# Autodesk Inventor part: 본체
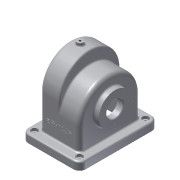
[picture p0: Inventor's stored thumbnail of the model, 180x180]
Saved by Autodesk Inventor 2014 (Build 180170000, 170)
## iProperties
Created: 2017-11
Part Number: 본체
Material: 알루미늄 6061
Document SubType Name: Modeling
Designer: user
Density: 2.71 g/cm^3
Appearance: 알루미늄 - 평지
Mass: 711.678 g
Surface Area: 1202.64 cm^2
Volume: 262.612 cm^3
Author: user
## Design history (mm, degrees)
sketch "스케치1"
  geometry: L1 (55, -75)-(-55, -75); L2 (-55, -75)-(-55, 75); L3 (-55, 75)-(55, 75); L4 (55, 75)-(55, -75); L5 (55, -75)-(-55, 75); L6 (-55, -75)-(55, 75); 1 further point
  constraints: 12 end point, 2 midpoint, 2 parallel, 1 horizontal, 1 perpendicular
  dimensions: "d0" = 110 distance of L1.start L1.end; "d1" = 150 distance of L1.end L2.end
extrude "돌출1" new body sketch "스케치1" distance "d2" = 15; taper "d3" = 0 deg
sketch "스케치2"
  geometry: L1 (-55, 15)-(55, 15) reference; L2 (-38, 15)-(-38, 138); L3 (-38, 138)-(0, 138); L4 (0, 138)-(0, 115); L5 (0, 115)-(38, 115); L6 (38, 115)-(38, 15); L7 (-55, 0)-(-55, 15) reference; L8 (-38, 15)-(38, 15); L9 (-5, 133)-(-33, 133); L10 (-33, 133)-(-33, 15); L11 (33, 15)-(33, 110); L12 (33, 110)-(-5, 110); L13 (-5, 110)-(-5, 133); 1 further point
  constraints: 22 end point, 4 parallel, 4 perpendicular, 4 point on line, 1 collinear, 1 other
  dimensions: "d4" = 76 horizontal distance of L5.end L2.end; "d5" = 38 distance of L2.end L3.end; "d6" = 55 distance from line of L3.end L7; "d13" = 5 distance between parallel lines of L3 L9; "d102" = 123 distance of L2.end L2.start; "d103" = 100 distance of L5.end L6.end
extrude "돌출2" new body sketch "스케치2" stored distance "d7" = 116; taper "d8" = 0 deg
fillet "모깎기1" dims "d9" = 58
fillet "모깎기2" dims "d10" = 58
fillet "모깎기3" dims "d11" = 3
fillet "모깎기4" dims "d12" = 8
feature "쉘1" dims "d14" = 2
sketch "스케치6"
  geometry: L1 (-30, 56)-(30, 56) reference; L2 (36, 50)-(36, -50) reference; L3 (-36, -50)-(-36, 50) reference; L4 (30, -56)-(-30, -56) reference; A1 r 6 centre (30, 50) between (36, 50) and (30, 56) reference; A2 r 6 centre (-30, 50) between (-30, 56) and (-36, 50) reference; A3 r 6 centre (-30, -50) between (-36, -50) and (-30, -56) reference; A4 r 6 centre (30, -50) between (30, -56) and (36, -50) reference; 1 further point
extrude "돌출3" cut sketch "스케치6" distance "d15" = 15; taper "d16" = 0 deg
fillet "모깎기5" dims "d17" = 12
hole "구멍1" diameter "d20" = 5; stored, may be unused: countersink angle "d24" = 90 deg, drill point angle "d26" = 0 deg; dims "d18" = 10, "d19" = 10, "d21" = 6, "d22" = 12, "d23" = 5, "d25" = 8
hole "구멍2" diameter "d29" = 5; stored, may be unused: countersink angle "d33" = 90 deg, drill point angle "d35" = 0 deg; dims "d27" = 10, "d28" = 10, "d30" = 6, "d31" = 12, "d32" = 5, "d34" = 8
hole "구멍3" diameter "d38" = 5; stored, may be unused: countersink angle "d42" = 90 deg, drill point angle "d44" = 0 deg; dims "d36" = 10, "d37" = 10, "d39" = 6, "d40" = 12, "d41" = 5, "d43" = 8
hole "구멍4" diameter "d47" = 5; stored, may be unused: countersink angle "d51" = 90 deg, drill point angle "d53" = 0 deg; dims "d45" = 10, "d46" = 10, "d48" = 6, "d49" = 12, "d50" = 5, "d52" = 8
fillet "모깎기6" dims "d54" = 3
sketch "스케치8"
  geometry: L1 (13, -15)-(-113, -15) reference; C1 r 31 at (-50, 50); A1 r 50 centre (-50, 42) between (0, 42) and (-100, 42) reference; 1 further point
  constraints: 1 centre point, 1 vertical alignment
  dimensions: "d59" = 65 distance from line of C1.centre L1; "d60" = 62 diameter of C1
extrude "돌출5" join sketch "스케치8" distance "d61" = 10; taper "d62" = 0 deg
fillet "모깎기8" dims "d63" = 3
sketch "스케치9"
  geometry: L1 (113, -15)-(-13, -15) reference; C1 r 37.5 at (50, 50); A1 r 50 centre (50, 65) between (100, 65) and (0, 65) reference; 1 further point
  constraints: 1 centre point, 1 vertical alignment
  dimensions: "d64" = 75 diameter of C1; "d65" = 65 distance from line of L1 C1.centre
extrude "돌출6" join sketch "스케치9" distance "d66" = 9; taper "d67" = 0 deg
fillet "모깎기9" dims "d68" = 3
sketch "스케치10" dims "d69" = 58
  geometry: C1 r 37.5 at (0, 0) reference; 3 further points
  constraints: 2 vertical alignment, 1 coincident, 2 other
hole "구멍5" sketch "스케치10" at (0, 29) diameter "d70" = 2; stored, may be unused: countersink angle "d74" = 82 deg, drill point angle "d76" = 118 deg; dims "d71" = 6, "d72" = 19, "d73" = 5, "d75" = 8
sketch "스케치11" dims "d80" = 52
  geometry: C1 r 31 at (0, 0) reference; 3 further points
  constraints: 2 vertical alignment, 1 coincident, 2 other
hole "구멍6" sketch "스케치11" at (0, 26) diameter "d81" = 2; stored, may be unused: countersink angle "d85" = 82 deg, drill point angle "d87" = 118 deg; dims "d82" = 6, "d83" = 19, "d84" = 5, "d86" = 8
sketch "스케치12"
  geometry: C1 r 37.5 at (0, 0) reference; C2 r 16 at (0, 0); 1 further point
  constraints: 1 centre point, 1 coincident
  dimensions: "d91" = 32 diameter of C2
extrude "돌출7" cut sketch "스케치12" stored distance "d92" = 9; taper "d93" = 0 deg
chamfer "모따기1" distance "d94" = 1; stored, may be unused: second distance "d95" = 2, angle "d96" = 45 deg
node "작업 평면1"
sketch "스케치13"
  geometry: L1 (38, 50)-(38, -50) reference; C1 r 6 at (19, 0); 1 further point
  constraints: 1 centre point, 1 horizontal alignment
  dimensions: "d98" = 12 diameter of C1; "d99" = 19 distance from line of C1.centre L1
extrude "돌출9" join sketch "스케치13" distance "d104" = 9; taper "d105" = 0 deg
fillet "모깎기10" dims "d106" = 3
hole "구멍7" diameter "d109" = 4; stored, may be unused: countersink angle "d113" = 82 deg, drill point angle "d115" = 118 deg; dims "d107" = 10, "d108" = 10, "d110" = 6, "d111" = 19, "d112" = 5, "d114" = 8
sketch "스케치14"
  geometry: L1 (43, 0)-(-43, 0) reference; L2 (-38, 80)-(-38, 15) reference; 2 further points
  constraints: 1 other
  dimensions: "d116" = 40 distance from line of L1 point (0, 40); "d117" = 38 distance from line of point (0, 40) L2
feature "결합1"
  node "솔리드2"
feature "엠보싱1" dims "d9" = 58, "d118" = 0.5, "d119" = 0
fillet "모깎기11" dims "d120" = 3
node "솔리드1"
pattern_circular "원형 패턴1" dims angle "d78" = 360 deg
pattern_circular "원형 패턴2" dims angle "d89" = 360 deg
other parameters: "d97" = 144
